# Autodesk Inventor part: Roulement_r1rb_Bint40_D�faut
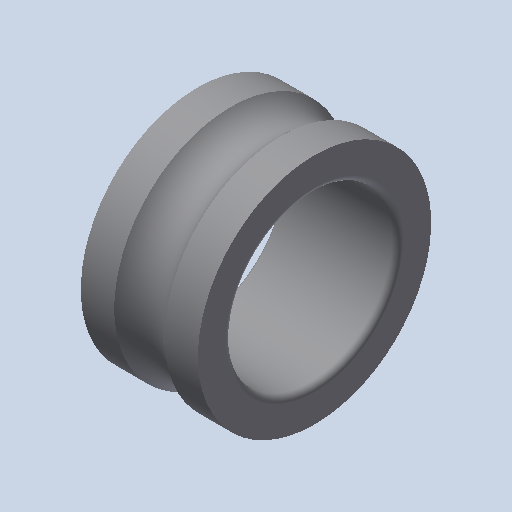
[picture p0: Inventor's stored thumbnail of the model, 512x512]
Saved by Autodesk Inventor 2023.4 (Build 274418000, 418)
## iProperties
Created: 2011-01
Part Number: Roulement_r1rb_Bint40_D�faut
Document SubType Name: Modeling
Designer: eric
Density: 1 g/cm^3
Mass: 2.35584 g
Surface Area: 19.7997 cm^2
Volume: 2.35584 cm^3
Material: Générique
Appearance: Par défaut
Author: eric
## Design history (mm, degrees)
feature "Base1"
node "Corps solides"
node "Corps surfaciques"
node "Solide1"
